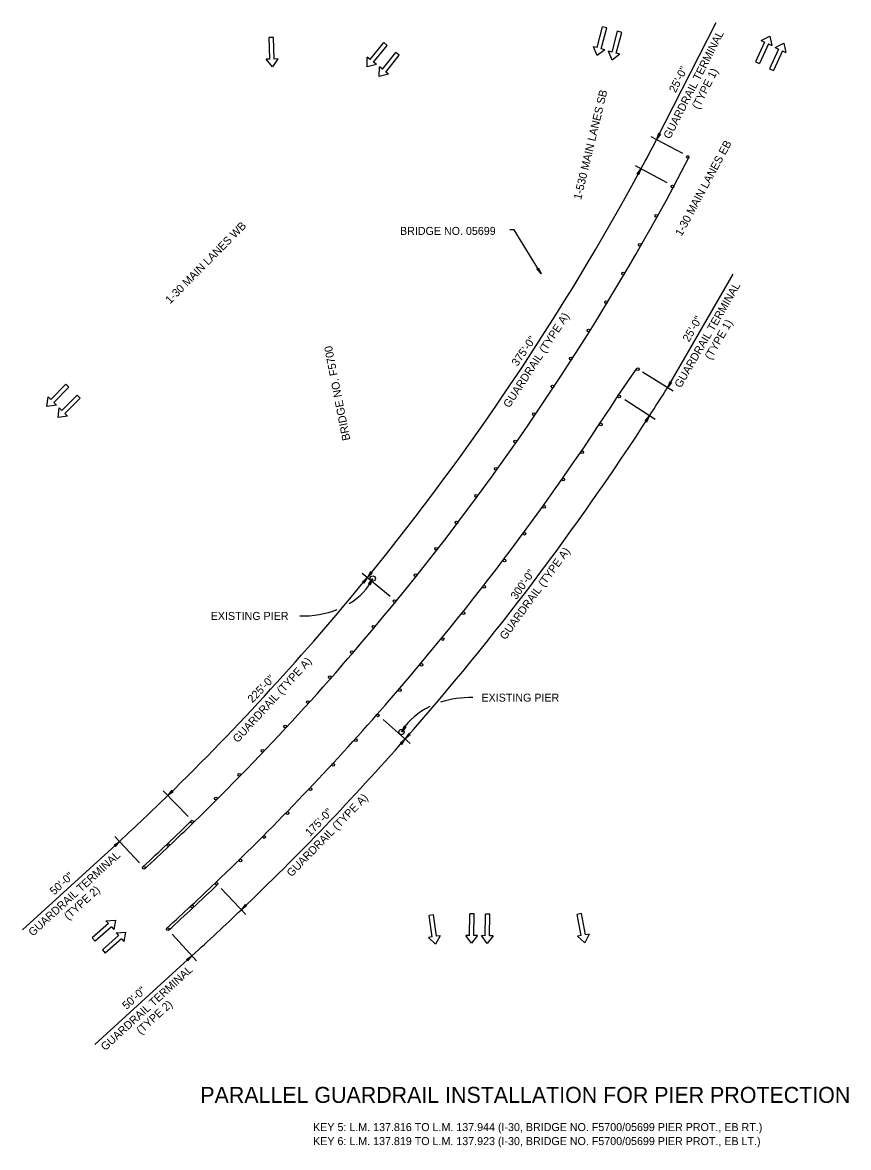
# Model space of a CAD drawing. Extents: x 1230537 to 1231758, y 2055794 to 2056784.
# Drawn here: x 1230537 to 1231157, y 2055859 to 2056702 of the extents above; entities that cross this region are included whole.
import ezdxf

# ---------------------------------------------------------------- set-up
doc = ezdxf.new("R2010")
doc.units = 0
for name, color, linetype in [('1', 7, 'Continuous'), ('2', 7, 'Continuous'), ('Default', 7, 'Continuous'), ('EOP', 7, 'Continuous'), ('GR', 7, 'Continuous')]:
    doc.layers.add(name, color=color, linetype=linetype)

msp = doc.modelspace()

# ---------------------------------------------------------------- linework, layer by layer
at = {"layer": '1'}
for p, q in [((1231014.59, 2056619.01), (1231013.06, 2056614.42)), ((1231015.87, 2056618.38), (1231013.06, 2056614.42)), ((1231014.71, 2056618.98), (1231013.44, 2056615.12)), ((1231015.78, 2056618.42), (1231013.44, 2056615.12)), ((1231014.85, 2056618.91), (1231013.82, 2056615.88)), ((1231015.65, 2056618.47), (1231013.82, 2056615.88)), ((1231014.93, 2056618.84), (1231014.17, 2056616.57)), ((1231015.55, 2056618.53), (1231014.17, 2056616.57)), ((1231015.02, 2056618.8), (1231014.52, 2056617.29)), ((1231015.42, 2056618.58), (1231014.52, 2056617.29)), ((1231015.87, 2056618.38), (1231014.59, 2056619.01)), ((1231015.12, 2056618.74), (1231014.91, 2056618.03)), ((1231015.33, 2056618.67), (1231014.91, 2056618.03)), ((1230998.56, 2056588.8), (1231001.47, 2056592.67)), ((1230998.65, 2056588.72), (1231001.1, 2056591.96)), ((1230999.72, 2056588.16), (1231001.1, 2056591.96)), ((1230999.8, 2056588.1), (1231001.47, 2056592.67)), ((1230999.8, 2056588.1), (1230998.56, 2056588.8)), ((1230998.79, 2056588.65), (1231000.7, 2056591.22)), ((1230998.89, 2056588.62), (1231000.33, 2056590.53)), ((1230998.98, 2056588.57), (1230999.93, 2056589.84)), ((1230999.08, 2056588.52), (1230999.55, 2056589.1)), ((1230999.26, 2056588.38), (1230999.55, 2056589.1)), ((1230999.38, 2056588.36), (1230999.93, 2056589.84)), ((1230999.5, 2056588.29), (1231000.33, 2056590.53)), ((1230999.6, 2056588.23), (1231000.7, 2056591.22)), ((1230906.15, 2056546.73), (1230902.96, 2056546.73)), ((1230926.31, 2056513.61), (1230906.15, 2056546.73)), ((1230923.19, 2056517.33), (1230924.41, 2056518.06)), ((1230923.19, 2056517.33), (1230926.31, 2056513.61)), ((1230923.28, 2056517.38), (1230925.88, 2056514.28)), ((1230923.4, 2056517.44), (1230925.44, 2056515)), ((1230923.5, 2056517.51), (1230925.03, 2056515.67)), ((1230923.62, 2056517.57), (1230924.63, 2056516.35)), ((1230923.71, 2056517.66), (1230924.18, 2056517.05)), ((1230923.91, 2056517.75), (1230924.18, 2056517.05)), ((1230924.01, 2056517.82), (1230924.63, 2056516.35)), ((1230924.1, 2056517.86), (1230925.03, 2056515.67)), ((1230924.17, 2056517.94), (1230925.44, 2056515)), ((1230924.3, 2056518.02), (1230925.88, 2056514.28)), ((1230924.41, 2056518.06), (1230926.31, 2056513.61)), ((1231023, 2056432.82), (1231021.21, 2056428.32)), ((1231024.24, 2056432.12), (1231021.21, 2056428.32)), ((1231023.11, 2056432.78), (1231021.63, 2056429)), ((1231024.15, 2056432.16), (1231021.63, 2056429)), ((1231023.24, 2056432.7), (1231022.05, 2056429.73)), ((1231024.02, 2056432.22), (1231022.05, 2056429.73)), ((1231023.32, 2056432.63), (1231022.44, 2056430.41)), ((1231023.92, 2056432.29), (1231022.44, 2056430.41)), ((1231023.41, 2056432.58), (1231022.83, 2056431.1)), ((1231023.8, 2056432.34), (1231022.83, 2056431.1)), ((1231024.24, 2056432.12), (1231023, 2056432.82)), ((1231023.51, 2056432.52), (1231023.25, 2056431.82)), ((1231023.72, 2056432.44), (1231023.25, 2056431.82)), ((1231004.56, 2056403.59), (1231007.77, 2056407.24)), ((1231004.65, 2056403.55), (1231007.32, 2056406.58)), ((1231005.65, 2056402.88), (1231007.32, 2056406.58)), ((1231005.76, 2056402.84), (1231007.77, 2056407.24)), ((1231004.56, 2056403.59), (1231005.76, 2056402.84)), ((1231004.77, 2056403.48), (1231006.86, 2056405.87)), ((1231004.86, 2056403.41), (1231006.44, 2056405.21)), ((1231004.98, 2056403.35), (1231006.02, 2056404.54)), ((1231005.06, 2056403.25), (1231005.56, 2056403.85)), ((1231005.26, 2056403.16), (1231005.56, 2056403.85)), ((1231005.36, 2056403.09), (1231006.02, 2056404.54)), ((1231005.45, 2056403.04), (1231006.44, 2056405.21)), ((1231005.52, 2056402.96), (1231006.86, 2056405.87)), ((1230798.45, 2056290.16), (1230795.98, 2056286)), ((1230799.56, 2056289.28), (1230795.98, 2056286)), ((1230798.55, 2056290.11), (1230796.49, 2056286.61)), ((1230799.48, 2056289.33), (1230796.49, 2056286.61)), ((1230798.67, 2056290.01), (1230797.02, 2056287.27)), ((1230799.37, 2056289.41), (1230797.02, 2056287.27)), ((1230798.74, 2056289.92), (1230797.52, 2056287.87)), ((1230799.28, 2056289.49), (1230797.52, 2056287.87)), ((1230798.82, 2056289.87), (1230798.01, 2056288.5)), ((1230799.17, 2056289.57), (1230798.01, 2056288.5)), ((1230799.56, 2056289.28), (1230798.45, 2056290.16)), ((1230798.91, 2056289.79), (1230798.54, 2056289.13)), ((1230799.1, 2056289.68), (1230798.54, 2056289.13)), ((1230792.39, 2056282.75), (1230795.98, 2056286)), ((1230793.48, 2056281.83), (1230792.39, 2056282.75)), ((1230792.47, 2056282.65), (1230795.48, 2056285.37)), ((1230792.59, 2056282.56), (1230794.94, 2056284.72)), ((1230792.68, 2056282.51), (1230794.45, 2056284.12)), ((1230792.75, 2056282.44), (1230793.93, 2056283.51)), ((1230792.85, 2056282.37), (1230793.42, 2056282.86)), ((1230793, 2056282.21), (1230793.42, 2056282.86)), ((1230793.12, 2056282.16), (1230793.93, 2056283.51)), ((1230793.21, 2056282.07), (1230794.45, 2056284.12)), ((1230793.31, 2056282), (1230794.94, 2056284.72)), ((1230793.41, 2056281.9), (1230795.48, 2056285.37)), ((1230793.48, 2056281.83), (1230795.98, 2056286)), ((1230797.07, 2056281.42), (1230800.04, 2056285.27)), ((1230797.07, 2056281.42), (1230798.32, 2056280.74)), ((1230797.17, 2056281.37), (1230799.63, 2056284.58)), ((1230797.29, 2056281.32), (1230799.22, 2056283.84)), ((1230797.39, 2056281.26), (1230798.84, 2056283.16)), ((1230797.51, 2056281.2), (1230798.47, 2056282.45)), ((1230797.6, 2056281.1), (1230798.05, 2056281.73)), ((1230797.81, 2056281.03), (1230798.05, 2056281.73)), ((1230797.91, 2056280.97), (1230798.47, 2056282.45)), ((1230798, 2056280.92), (1230798.84, 2056283.16)), ((1230798.08, 2056280.85), (1230799.22, 2056283.84)), ((1230798.21, 2056280.77), (1230799.63, 2056284.58)), ((1230798.32, 2056280.74), (1230800.04, 2056285.27)), ((1230823.58, 2056174.48), (1230821.59, 2056170.07)), ((1230824.79, 2056173.72), (1230821.59, 2056170.07)), ((1230823.7, 2056174.44), (1230822.04, 2056170.73)), ((1230824.7, 2056173.77), (1230822.04, 2056170.73)), ((1230823.82, 2056174.35), (1230822.49, 2056171.44)), ((1230824.58, 2056173.83), (1230822.49, 2056171.44)), ((1230823.9, 2056174.27), (1230822.92, 2056172.1)), ((1230824.48, 2056173.9), (1230822.92, 2056172.1)), ((1230823.99, 2056174.23), (1230823.33, 2056172.78)), ((1230824.37, 2056173.97), (1230823.33, 2056172.78)), ((1230824.79, 2056173.72), (1230823.58, 2056174.48)), ((1230824.08, 2056174.16), (1230823.79, 2056173.47)), ((1230824.28, 2056174.07), (1230823.79, 2056173.47)), ((1230820.7, 2056161.82), (1230824.4, 2056164.94)), ((1230821.75, 2056160.86), (1230820.7, 2056161.82)), ((1230820.77, 2056161.72), (1230823.88, 2056164.33)), ((1230820.88, 2056161.62), (1230823.32, 2056163.7)), ((1230820.98, 2056161.57), (1230822.8, 2056163.11)), ((1230821.05, 2056161.5), (1230822.26, 2056162.52)), ((1230821.14, 2056161.43), (1230821.72, 2056161.89)), ((1230821.28, 2056161.26), (1230821.72, 2056161.89)), ((1230821.4, 2056161.21), (1230822.26, 2056162.52)), ((1230821.49, 2056161.11), (1230822.8, 2056163.11)), ((1230821.59, 2056161.04), (1230823.32, 2056163.7)), ((1230821.68, 2056160.94), (1230823.88, 2056164.33)), ((1230821.75, 2056160.86), (1230824.4, 2056164.94)), ((1230827.02, 2056169), (1230824.4, 2056164.94)), ((1230828.1, 2056168.08), (1230824.4, 2056164.94)), ((1230827.13, 2056168.95), (1230824.94, 2056165.53)), ((1230828.02, 2056168.14), (1230824.94, 2056165.53)), ((1230827.24, 2056168.84), (1230825.49, 2056166.17)), ((1230827.91, 2056168.22), (1230825.49, 2056166.17)), ((1230827.3, 2056168.76), (1230826.01, 2056166.75)), ((1230827.83, 2056168.3), (1230826.01, 2056166.75)), ((1230827.38, 2056168.7), (1230826.52, 2056167.36)), ((1230827.72, 2056168.38), (1230826.52, 2056167.36)), ((1230828.1, 2056168.08), (1230827.02, 2056169)), ((1230827.47, 2056168.61), (1230827.08, 2056167.97)), ((1230827.65, 2056168.5), (1230827.08, 2056167.97)), ((1230649.13, 2056126.39), (1230646.2, 2056122.54)), ((1230650.14, 2056125.39), (1230646.2, 2056122.54)), ((1230649.23, 2056126.33), (1230646.78, 2056123.09)), ((1230650.06, 2056125.46), (1230646.78, 2056123.09)), ((1230649.33, 2056126.22), (1230647.39, 2056123.68)), ((1230649.96, 2056125.54), (1230647.39, 2056123.68)), ((1230649.39, 2056126.13), (1230647.95, 2056124.22)), ((1230649.88, 2056125.63), (1230647.95, 2056124.22)), ((1230649.46, 2056126.06), (1230648.5, 2056124.79)), ((1230649.78, 2056125.72), (1230648.5, 2056124.79)), ((1230649.54, 2056125.97), (1230649.11, 2056125.36)), ((1230649.72, 2056125.84), (1230649.11, 2056125.36)), ((1230650.14, 2056125.39), (1230649.13, 2056126.39)), ((1230605.99, 2056085.33), (1230609.94, 2056088.11)), ((1230606.05, 2056085.22), (1230609.38, 2056087.55)), ((1230606.16, 2056085.12), (1230608.76, 2056086.97)), ((1230606.25, 2056085.06), (1230608.2, 2056086.43)), ((1230606.31, 2056084.98), (1230607.61, 2056085.89)), ((1230606.63, 2056084.65), (1230607.61, 2056085.89)), ((1230606.72, 2056084.55), (1230608.2, 2056086.43)), ((1230606.81, 2056084.47), (1230608.76, 2056086.97)), ((1230606.89, 2056084.36), (1230609.38, 2056087.55)), ((1230606.95, 2056084.28), (1230609.94, 2056088.11)), ((1230606.95, 2056084.28), (1230605.99, 2056085.33)), ((1230606.4, 2056084.9), (1230607.02, 2056085.31)), ((1230606.52, 2056084.71), (1230607.02, 2056085.31)), ((1230704.4, 2056040.7), (1230701.43, 2056036.88)), ((1230705.39, 2056039.69), (1230701.43, 2056036.88)), ((1230704.5, 2056040.64), (1230702.02, 2056037.42)), ((1230705.32, 2056039.75), (1230702.02, 2056037.42)), ((1230704.6, 2056040.52), (1230702.63, 2056038.01)), ((1230705.22, 2056039.84), (1230702.63, 2056038.01)), ((1230704.65, 2056040.43), (1230703.19, 2056038.54)), ((1230705.14, 2056039.93), (1230703.19, 2056038.54)), ((1230704.73, 2056040.36), (1230703.76, 2056039.11)), ((1230705.04, 2056040.02), (1230703.76, 2056039.11)), ((1230704.81, 2056040.27), (1230704.37, 2056039.67)), ((1230704.98, 2056040.14), (1230704.37, 2056039.67)), ((1230705.39, 2056039.69), (1230704.4, 2056040.7)), ((1230660.35, 2055999.5), (1230664.31, 2056002.29)), ((1230660.41, 2055999.4), (1230663.74, 2056001.72)), ((1230661.26, 2055998.54), (1230663.74, 2056001.72)), ((1230661.32, 2055998.46), (1230664.31, 2056002.29)), ((1230661.32, 2055998.46), (1230660.35, 2055999.5)), ((1230660.52, 2055999.29), (1230663.13, 2056001.14)), ((1230660.61, 2055999.23), (1230662.56, 2056000.6)), ((1230660.68, 2055999.15), (1230661.98, 2056000.07)), ((1230660.76, 2055999.07), (1230661.38, 2055999.48)), ((1230660.89, 2055998.89), (1230661.38, 2055999.48)), ((1230661, 2055998.83), (1230661.98, 2056000.07)), ((1230661.09, 2055998.72), (1230662.56, 2056000.6)), ((1230661.17, 2055998.64), (1230663.13, 2056001.14))]:
    msp.add_line(p, q, dxfattribs=at)
at = {"layer": 'Default'}
for p, q in [((1230968.35, 2056683.36), (1230972.51, 2056699.03)), ((1230971.55, 2056682.51), (1230975.71, 2056698.18)), ((1230975.71, 2056698.18), (1230972.51, 2056699.03)), ((1230979.62, 2056680), (1230983.78, 2056695.67)), ((1230982.81, 2056679.16), (1230986.97, 2056694.82)), ((1230986.97, 2056694.82), (1230983.78, 2056695.67)), ((1230725.65, 2056690.98), (1230722.34, 2056690.88)), ((1230722.87, 2056674.68), (1230722.34, 2056690.88)), ((1230726.17, 2056674.78), (1230725.65, 2056690.98)), ((1230798.09, 2056674.5), (1230808.25, 2056687.14)), ((1230800.66, 2056672.43), (1230810.82, 2056685.07)), ((1230810.82, 2056685.07), (1230808.25, 2056687.14)), ((1231094.09, 2056687.49), (1231087.3, 2056672.78)), ((1231097.09, 2056686.11), (1231090.3, 2056671.39)), ((1231091.59, 2056688.65), (1231097.99, 2056691.99)), ((1231091.59, 2056688.65), (1231094.09, 2056687.49)), ((1231097.09, 2056686.11), (1231099.59, 2056684.95)), ((1231097.99, 2056691.99), (1231099.59, 2056684.95)), ((1231102.11, 2056683.4), (1231108.51, 2056686.75)), ((1231108.51, 2056686.75), (1231110.11, 2056679.71)), ((1230795.79, 2056669.01), (1230795.94, 2056676.23)), ((1230798.09, 2056674.5), (1230795.94, 2056676.23)), ((1230807.25, 2056667.14), (1230817.41, 2056679.77)), ((1230809.82, 2056665.07), (1230819.98, 2056677.7)), ((1230819.98, 2056677.7), (1230817.41, 2056679.77)), ((1230968.35, 2056683.36), (1230965.69, 2056684.07)), ((1230968.48, 2056677.41), (1230965.69, 2056684.07)), ((1230974.21, 2056681.81), (1230968.48, 2056677.41)), ((1230974.21, 2056681.81), (1230971.55, 2056682.51)), ((1230979.62, 2056680), (1230976.95, 2056680.71)), ((1230979.74, 2056674.05), (1230976.95, 2056680.71)), ((1230985.47, 2056678.45), (1230979.74, 2056674.05)), ((1230985.47, 2056678.45), (1230982.81, 2056679.16)), ((1231104.61, 2056682.25), (1231097.81, 2056667.53)), ((1231107.61, 2056680.86), (1231100.82, 2056666.14)), ((1231102.11, 2056683.4), (1231104.61, 2056682.25)), ((1231107.61, 2056680.86), (1231110.11, 2056679.71)), ((1230722.87, 2056674.68), (1230720.11, 2056674.59)), ((1230724.7, 2056669.01), (1230720.11, 2056674.59)), ((1230728.92, 2056674.87), (1230724.7, 2056669.01)), ((1230728.92, 2056674.87), (1230726.17, 2056674.78)), ((1230802.81, 2056670.71), (1230795.79, 2056669.01)), ((1230802.81, 2056670.71), (1230800.66, 2056672.43)), ((1230804.95, 2056661.65), (1230805.1, 2056668.87)), ((1230807.25, 2056667.14), (1230805.1, 2056668.87)), ((1231087.3, 2056672.78), (1231090.3, 2056671.39)), ((1230811.97, 2056663.34), (1230804.95, 2056661.65)), ((1230811.97, 2056663.34), (1230809.82, 2056665.07)), ((1231097.81, 2056667.53), (1231100.82, 2056666.14)), ((1230558.34, 2056419.56), (1230569.74, 2056431.08)), ((1230560.69, 2056417.23), (1230572.09, 2056428.75)), ((1230572.09, 2056428.75), (1230569.74, 2056431.08)), ((1230555.49, 2056414.33), (1230556.38, 2056421.5)), ((1230562.65, 2056415.3), (1230555.49, 2056414.33)), ((1230558.34, 2056419.56), (1230556.38, 2056421.5)), ((1230562.65, 2056415.3), (1230560.69, 2056417.23)), ((1230566.69, 2056411.29), (1230578.1, 2056422.81)), ((1230569.04, 2056408.97), (1230580.45, 2056420.49)), ((1230580.45, 2056420.49), (1230578.1, 2056422.81)), ((1230563.85, 2056406.06), (1230564.74, 2056413.23)), ((1230571, 2056407.03), (1230563.85, 2056406.06)), ((1230566.69, 2056411.29), (1230564.74, 2056413.23)), ((1230571, 2056407.03), (1230569.04, 2056408.97)), ((1230599.85, 2056028.54), (1230607.06, 2056029.05)), ((1230599.85, 2056028.54), (1230601.69, 2056026.48)), ((1230607.06, 2056029.05), (1230605.72, 2056021.96)), ((1230845.53, 2056032.98), (1230842.27, 2056032.48)), ((1230844.69, 2056016.46), (1230842.27, 2056032.48)), ((1230847.96, 2056016.95), (1230845.53, 2056032.98)), ((1230872.6, 2056017.59), (1230872.88, 2056033.8)), ((1230876.19, 2056033.74), (1230872.88, 2056033.8)), ((1230875.91, 2056017.53), (1230876.19, 2056033.74)), ((1230884.35, 2056017.39), (1230884.63, 2056033.59)), ((1230887.94, 2056033.54), (1230884.63, 2056033.59)), ((1230887.66, 2056017.33), (1230887.94, 2056033.54)), ((1230956.59, 2056033.99), (1230953.35, 2056033.36)), ((1230956.43, 2056017.44), (1230953.35, 2056033.36)), ((1230959.68, 2056018.07), (1230956.59, 2056033.99)), ((1230601.69, 2056026.48), (1230589.59, 2056015.69)), ((1230603.89, 2056024.01), (1230591.79, 2056013.22)), ((1230603.89, 2056024.01), (1230605.72, 2056021.96)), ((1230607.41, 2056019.53), (1230614.61, 2056020.05)), ((1230607.41, 2056019.53), (1230609.24, 2056017.48)), ((1230614.61, 2056020.05), (1230613.28, 2056012.95)), ((1230962.38, 2056018.6), (1230959.15, 2056012.14)), ((1230962.38, 2056018.6), (1230959.68, 2056018.07)), ((1230589.59, 2056015.69), (1230591.79, 2056013.22)), ((1230609.24, 2056017.48), (1230597.14, 2056006.69)), ((1230611.44, 2056015.01), (1230599.34, 2056004.22)), ((1230611.44, 2056015.01), (1230613.28, 2056012.95)), ((1230844.69, 2056016.46), (1230841.97, 2056016.04)), ((1230847.18, 2056011.05), (1230841.97, 2056016.04)), ((1230850.68, 2056017.36), (1230847.18, 2056011.05)), ((1230850.68, 2056017.36), (1230847.96, 2056016.95)), ((1230872.6, 2056017.59), (1230869.85, 2056017.64)), ((1230874.16, 2056011.84), (1230869.85, 2056017.64)), ((1230878.66, 2056017.48), (1230874.16, 2056011.84)), ((1230878.66, 2056017.48), (1230875.91, 2056017.53)), ((1230884.35, 2056017.39), (1230881.6, 2056017.43)), ((1230885.91, 2056011.64), (1230881.6, 2056017.43)), ((1230890.41, 2056017.28), (1230885.91, 2056011.64)), ((1230890.41, 2056017.28), (1230887.66, 2056017.33)), ((1230956.43, 2056017.44), (1230953.73, 2056016.92)), ((1230959.15, 2056012.14), (1230953.73, 2056016.92)), ((1230597.14, 2056006.69), (1230599.34, 2056004.22))]:
    msp.add_line(p, q, dxfattribs=at)
for centre, major_axis, start_param, end_param in [((1230743.29, 2056303.87), (60.05, -7.33), 5.511151, 6.031138), ((1230743.29, 2056303.87), (60.05, -7.33), 4.837778, 5.329022), ((1230877.18, 2056149.22), (-60.05, 7.33), 4.837778, 5.25813), ((1230877.18, 2056149.22), (-60.05, 7.33), 5.411699, 5.936648)]:
    msp.add_ellipse(centre, major_axis=major_axis, ratio=0.768281, start_param=start_param, end_param=end_param, dxfattribs=at)
at = {"layer": 'EOP'}
for centre in [(1230800.04, 2056285.27), (1230821.59, 2056170.07)]:
    msp.add_circle(centre, 2, dxfattribs=at)
at = {"layer": 'GR'}
for p, q in [((1231013.06, 2056614.42), (1231057.72, 2056702.2)), ((1231008.63, 2056616.74), (1231032.54, 2056604.2)), ((1230997.07, 2056595.05), (1231020.82, 2056582.2)), ((1231021.21, 2056428.32), (1231070.6, 2056513.53)), ((1230792.1, 2056289.16), (1230813.01, 2056272.08)), ((1230828.15, 2056161.63), (1230807.88, 2056179.48)), ((1230642.71, 2056126.12), (1230661.55, 2056106.78)), ((1230537.18, 2056021.74), (1230609.94, 2056088.11)), ((1230606.55, 2056091.78), (1230624.89, 2056071.97)), ((1230704.88, 2056033.26), (1230686.24, 2056052.79)), ((1230667.67, 2055998.59), (1230649.51, 2056018.57)), ((1230591.55, 2055935.91), (1230664.31, 2056002.29))]:
    msp.add_line(p, q, dxfattribs=at)
for points in [[(1231026.1, 2056579.35), (1231037.6, 2056601.55)], [(1230984.26, 2056422.43), (1230998.11, 2056442.85)], [(1231025.44, 2056425.66), (1231002.59, 2056440.03)], [(1231011.97, 2056404.53), (1230989.29, 2056419.18)]]:
    msp.add_lwpolyline(points, dxfattribs=at)
for centre in [(1231036.38, 2056601.37), (1231024.88, 2056579.19), (1231012.85, 2056557.29), (1231000.54, 2056535.55), (1230987.96, 2056513.96), (1230975.1, 2056492.53), (1230961.98, 2056471.27), (1230948.59, 2056450.17), (1230998.95, 2056442.31), (1230934.94, 2056429.24), (1230984.96, 2056421.72), (1230921.02, 2056408.49), (1230971.25, 2056400.8), (1230906.84, 2056387.91), (1230957.29, 2056380.05), (1230892.41, 2056367.52), (1230943.06, 2056359.47), (1230877.71, 2056347.31), (1230928.59, 2056339.07), (1230862.77, 2056327.28), (1230913.87, 2056318.85), (1230847.57, 2056307.45), (1230898.89, 2056298.82), (1230832.12, 2056287.81), (1230883.68, 2056278.97), (1230816.43, 2056268.36), (1230868.21, 2056259.31), (1230800.49, 2056249.12), (1230852.51, 2056239.84), (1230784.32, 2056230.08), (1230836.57, 2056220.57), (1230767.9, 2056211.24), (1230820.39, 2056201.5), (1230751.24, 2056192.61), (1230803.97, 2056182.62), (1230734.36, 2056174.19), (1230787.33, 2056163.95), (1230717.24, 2056155.99), (1230770.45, 2056145.49), (1230699.89, 2056138.01), (1230753.35, 2056127.24), (1230682.32, 2056120.24), (1230664.53, 2056102.7), (1230736.03, 2056109.2), (1230646.51, 2056085.38), (1230718.48, 2056091.37), (1230628.28, 2056068.3), (1230700.72, 2056073.77), (1230682.74, 2056056.38), (1230664.54, 2056039.22), (1230646.14, 2056022.28)]:
    msp.add_circle(centre, 1, dxfattribs=at)
for radius, start, end in [(1954, 331.59446, 332.31716), (1954, 320.75393, 331.59446), (1982, 320.75393, 331.59446), (2054, 327.1238, 327.82117), (2026, 318.63973, 327.1238), (2054, 318.63973, 327.1238), (1954, 314.24962, 320.75393), (1982, 314.24962, 320.75393), (2026, 313.6858, 318.63973), (2054, 313.6858, 318.63973), (1954, 312.78351, 314.24962), (1980, 312.78351, 314.24962), (1982, 312.78351, 314.24962), (2026, 312.27039, 313.6858), (2028, 312.27039, 313.6858), (2054, 312.27039, 313.6858)]:
    msp.add_arc((1229282.73, 2057522.2), radius, start, end, dxfattribs=at)

# ---------------------------------------------------------------- texts
at = {"layer": '1'}
for s, height, rotation, p in [('GUARDRAIL TERMINAL', 6, 63.03532, (1231023.09, 2056614.3)), ('25\'-0"', 6, 63.03532, (1231027.32, 2056649.07)), ('(TYPE 1)', 6, 63.03532, (1231044.55, 2056636.62)), ('BRIDGE NO. 05699', 6, 0.00003, (1230820.49, 2056542.91)), ('GUARDRAIL TERMINAL', 6, 59.90147, (1231031.23, 2056427.65)), ('GUARDRAIL (TYPE A)', 6, 56.84142, (1230902.52, 2056412.71)), ('25\'-0"', 6, 59.90147, (1231037.34, 2056462.13)), ('(TYPE 1)', 6, 59.90147, (1231053.87, 2056448.76)), ('375\'-0"', 6, 55.1311, (1230908.64, 2056443.94)), ('GUARDRAIL (TYPE A)', 6, 53.88615, (1230899.56, 2056238.81)), ('300\'-0"', 6, 55.1311, (1230907.83, 2056268.94)), ('GUARDRAIL (TYPE A)', 6, 47.57302, (1230698.72, 2056161.64)), ('225\'-0"', 6, 45.99505, (1230709.73, 2056191.52)), ('GUARDRAIL (TYPE A)', 6, 45.69336, (1230739.05, 2056061.05)), ('175\'-0"', 6, 45.99505, (1230753.02, 2056091.44)), ('GUARDRAIL TERMINAL', 6, 42.37251, (1230544.91, 2056016.6)), ('50\'-0"', 6, 42.37251, (1230560.96, 2056047.49)), ('(TYPE 2)', 6, 42.37251, (1230571.6, 2056028.77)), ('GUARDRAIL TERMINAL', 6, 42.37251, (1230599.27, 2055930.78)), ('50\'-0"', 6, 42.37251, (1230615.32, 2055961.66)), ('(TYPE 2)', 6, 42.37251, (1230625.97, 2055942.95)), ('PARALLEL GUARDRAIL INSTALLATION FOR PIER PROTECTION', 12, 0.00003, (1230670.63, 2055892.01))]:
    msp.add_text(s, height=height, rotation=rotation, dxfattribs=at).set_placement(p)
for s, p in [('KEY 5: L.M. 137.816 TO L.M. 137.944 (I-30, BRIDGE NO. F5700/05699 PIER PROT., EB RT.)', (1230755.28, 2055870.86)), ('KEY 6: L.M. 137.819 TO L.M. 137.923 (I-30, BRIDGE NO. F5700/05699 PIER PROT., EB LT.)', (1230755.28, 2055860.36))]:
    msp.add_text(s, height=6, dxfattribs=at).set_placement(p)
at = {"layer": '2'}
for s, rotation, p in [('1-530 MAIN LANES SB', 76.45539, (1230956.41, 2056568.96)), ('1-30 MAIN LANES EB', 61.75739, (1231031.78, 2056541.46)), ('1-30 MAIN LANES WB', 45.34864, (1230647.94, 2056490.82)), ('BRIDGE NO. F5700', 101.06977, (1230783.25, 2056389.25))]:
    msp.add_text(s, height=6, rotation=rotation, dxfattribs=at).set_placement(p)
at = {"layer": 'Default'}
for p in [(1230678.45, 2056254.18), (1230881.6, 2056192.91)]:
    msp.add_text('EXISTING PIER', height=6, dxfattribs=at).set_placement(p)

doc.saveas('drawing.dxf')
